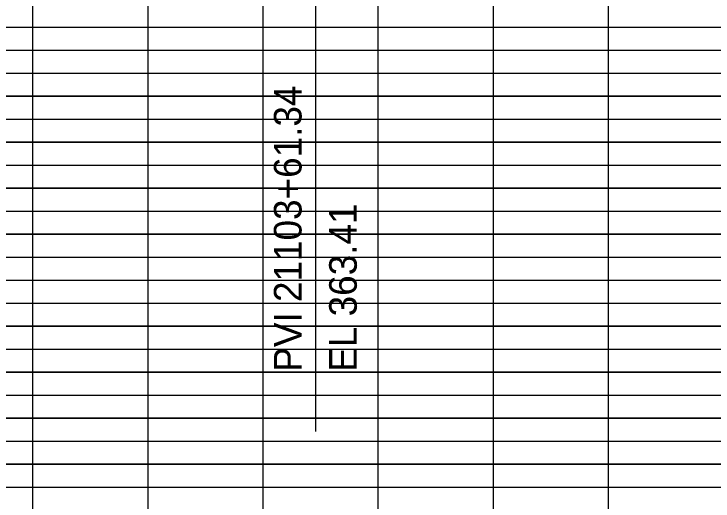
# Model space of a CAD drawing. Extents: x 1195880 to 1289360, y 2059330 to 2086925.
# Drawn here: x 1197302.3 to 1197454.1, y 2059552.7 to 2059658.6 of the extents above; entities that cross this region are included whole.
import ezdxf

# ---------------------------------------------------------------- set-up
doc = ezdxf.new("R2010")
doc.units = 0
doc.layers.add('Grid', color=7, linetype='Continuous')
doc.layers.add('Profile Annotation', color=7, linetype='Continuous')

msp = doc.modelspace()

# ---------------------------------------------------------------- linework, layer by layer
at = {"layer": 'Grid'}
for p, q in [((1197306.37, 2059350.74), (1197306.37, 2059950.74)), ((1197331.37, 2059350.74), (1197331.37, 2059950.74)), ((1197356.37, 2059350.74), (1197356.37, 2059950.74)), ((1197381.37, 2059350.74), (1197381.37, 2059950.74)), ((1197406.37, 2059350.74), (1197406.37, 2059950.74)), ((1197431.37, 2059350.74), (1197431.37, 2059950.74)), ((1197006.37, 2059655.74), (1198006.37, 2059655.74)), ((1197006.37, 2059650.74), (1198006.37, 2059650.74)), ((1197006.37, 2059645.74), (1198006.37, 2059645.74)), ((1197006.37, 2059640.74), (1198006.37, 2059640.74)), ((1198006.37, 2059640.74), (1197006.37, 2059640.74)), ((1197006.37, 2059635.74), (1198006.37, 2059635.74)), ((1197006.37, 2059630.74), (1198006.37, 2059630.74)), ((1198006.37, 2059630.74), (1197006.37, 2059630.74)), ((1197006.37, 2059625.74), (1198006.37, 2059625.74)), ((1197006.37, 2059620.74), (1198006.37, 2059620.74)), ((1198006.37, 2059620.74), (1197006.37, 2059620.74)), ((1197006.37, 2059615.74), (1198006.37, 2059615.74)), ((1197006.37, 2059610.74), (1198006.37, 2059610.74)), ((1198006.37, 2059610.74), (1197006.37, 2059610.74)), ((1197006.37, 2059605.74), (1198006.37, 2059605.74)), ((1197006.37, 2059600.74), (1198006.37, 2059600.74)), ((1197006.37, 2059595.74), (1198006.37, 2059595.74)), ((1197006.37, 2059590.74), (1198006.37, 2059590.74)), ((1198006.37, 2059590.74), (1197006.37, 2059590.74)), ((1197006.37, 2059585.74), (1198006.37, 2059585.74)), ((1197006.37, 2059580.74), (1198006.37, 2059580.74)), ((1198006.37, 2059580.74), (1197006.37, 2059580.74)), ((1197006.37, 2059575.74), (1198006.37, 2059575.74)), ((1197006.37, 2059570.74), (1198006.37, 2059570.74)), ((1198006.37, 2059570.74), (1197006.37, 2059570.74)), ((1197006.37, 2059565.74), (1198006.37, 2059565.74)), ((1197006.37, 2059560.74), (1198006.37, 2059560.74)), ((1198006.37, 2059560.74), (1197006.37, 2059560.74)), ((1197006.37, 2059555.74), (1198006.37, 2059555.74))]:
    msp.add_line(p, q, dxfattribs=at)
at = {"layer": 'Profile Annotation'}
msp.add_line((1197367.71, 2059667.81), (1197367.71, 2059567.81), dxfattribs=at)

# ---------------------------------------------------------------- texts
for s, p in [('PVI 21103+61.34', (1197364.71, 2059580.81)), ('EL 363.41', (1197376.71, 2059580.81))]:
    msp.add_text(s, height=6, rotation=90, dxfattribs=at).set_placement(p)

doc.saveas('drawing.dxf')
